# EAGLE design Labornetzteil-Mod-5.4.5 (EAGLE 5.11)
OC_FARNELL: unknown
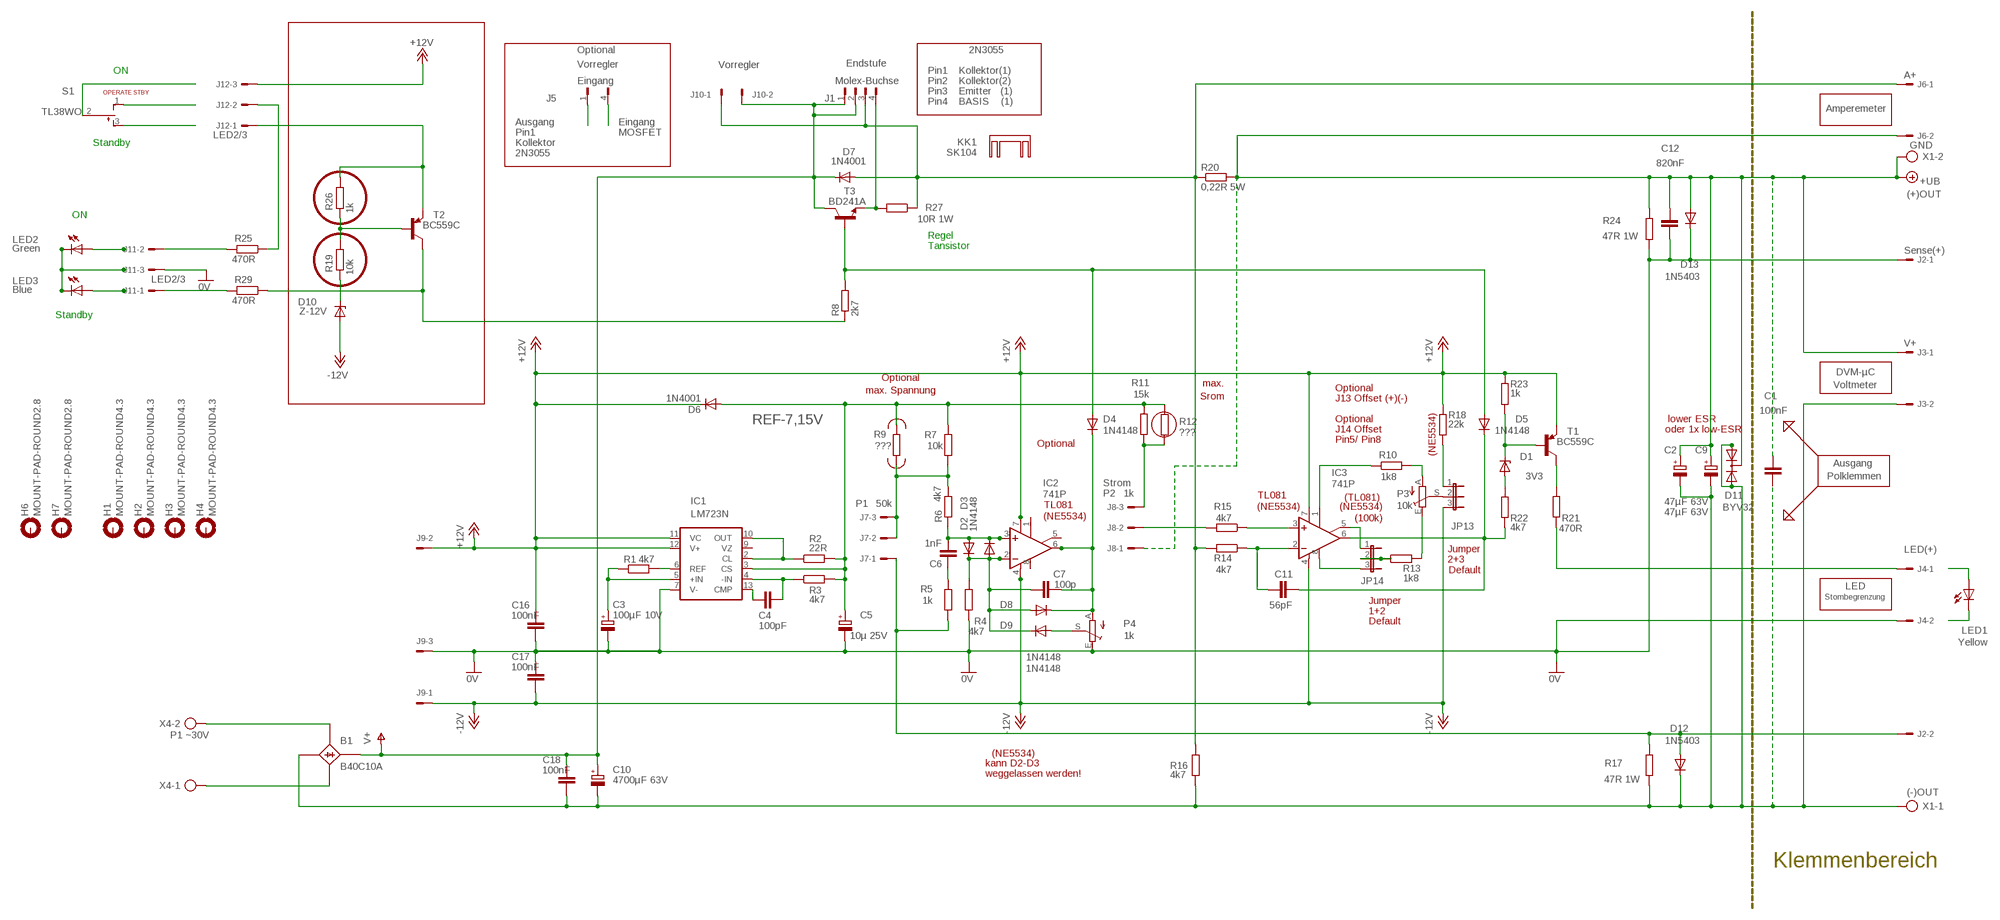
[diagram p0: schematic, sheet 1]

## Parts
B1  B40C10A  B25A-  [B25A-]
C1  100nF  C-EU025-024X044  [C025-024X044]
C2  47µF 63V  CPOL-EUE2.5-6  [E2,5-6]
C3  100µF 10V  CPOL-EUE5-8.5  [E5-8,5]
C4  100pF  C-EU025-024X044  [C025-024X044]
C5  10µ 25V  CPOL-EUE5-8.5  [E5-8,5]
C6  1nF  C-EU025-024X044  [C025-024X044]
C7  100p  C-EU025-024X044  [C025-024X044]
C9  47µF 63V  CPOL-EUE2.5-6  [E2,5-6]
C10  4700µF 63V  CPOL-EUE10-35  [EB35D]
C11  56pF  C-EU025-024X044  [C025-024X044]
C12  820nF  C-EU025-024X044  [C025-024X044]
C16  100nF  C-EU025-030X050  [C025-030X050]
C17  100nF  C-EU025-024X044  [C025-024X044]
C18  100nF  C-EUC1206K  [C1206K]
D1  3V3  ZENER-DIODEDO34-7  [DO34Z7]
D2  1N4148  1N4148DO35-10  [DO35-10]
D3  1N4148  1N4148DO35-10  [DO35-10]
D4  1N4148  1N4148DO35-10  [DO35-10]
D5  1N4148  1N4148DO35-10  [DO35-10]
D6  1N4001  1N4004  [DO41-10]
D7  1N4001  1N4004  [DO41-10]
D8  1N4148  DIODE-D-2.5  [D-2.5]
D9  1N4148  DIODE-D-2.5  [D-2.5]
D10  Z-12V  ZENER-DIODEZD-5  [ZDIO-5]
D11  BYV32  [TO220ABS]
D12  1N5403  DIODE-D-5  [D-5]
D13  1N5403  DIODE-D-5  [D-5]
H1  MOUNT-PAD-ROUND4.3  [4,3-PAD]
H2  MOUNT-PAD-ROUND4.3  [4,3-PAD]
H3  MOUNT-PAD-ROUND4.3  [4,3-PAD]
H4  MOUNT-PAD-ROUND4.3  [4,3-PAD]
H6  MOUNT-PAD-ROUND2.8  [2,8-PAD]
H7  MOUNT-PAD-ROUND2.8  [2,8-PAD]
IC1  LM723N  [DIL14]
IC2  741P  [DIL08]
IC3  741P  [DIL08]
J1  Endstufe  FLOPPY-4  [FLOPPY-4]
J2  Sense(+)  22-27-2021-02  [6410-02]
J3  V+  22-27-2021-02  [6410-02]
J4  LED(+)  22-27-2021-02  [6410-02]
J5  Vorregler  FLOPPY-4/2HALF  [FLOPPY-4/2]
J6  A+  22-27-2021-02  [6410-02]
J7  Spannung  22-27-2031-03  [6410-03]
J8  Strom  22-27-2031-03  [6410-03]
J9  -12V  22-27-2031-03  [6410-03]
J10  Vorregler  22-27-2021-02  [6410-02]
J11  LED2/3  22-27-2031-03  [6410-03]
J12  LED2/3  22-27-2031-03  [6410-03]
JP13  JP2E  [JP2]
JP14  JP2E  [JP2]
KK1  SK104  [SK104]
LED1  Yellow  LED5MM  [LED5MM]
LED2  Green  LED5MM  [LED5MM]
LED3  Blue  LED5MM  [LED5MM]
P3  10k  TRIM_EU-CA6V  [CA6V]
P4  1k  TRIM_EU-S63X  [S63X]
R1  4k7  R-EU_0204/2V  [0204V]
R2  22R  R-EU_0204/2V  [0204V]
R3  4k7  R-EU_0204/2V  [0204V]
R4  4k7  R-EU_0207/10  [0207/10]
R5  1k  R-EU_0207/10  [0207/10]
R6  4k7  R-EU_0207/10  [0207/10]
R7  10k  R-EU_0207/10  [0207/10]
R8  2k7  R-EU_0204/2V  [0204V]
R9  ???  R-EU_0207/10  [0207/10]
R10  1k8  R-EU_0207/10  [0207/10]
R11  15k  R-EU_0207/10  [0207/10]
R12  ???  R-EU_0207/10  [0207/10]
R13  1k8  R-EU_0207/10  [0207/10]
R14  4k7  R-EU_0207/10  [0207/10]
R15  4k7  R-EU_0207/10  [0207/10]
R16  4k7  R-EU_0207/10  [0207/10]
R17  47R 1W  R-EU_0207/10  [0207/10]
R18  22k  R-EU_0204/2V  [0204V]
R19  10k  R-EU_0204/2V  [0204V]
R20  0,22R 5W  R-EU_0617/22  [0617/22]
R21  470R  R-EU_0207/10  [0207/10]
R22  4k7  R-EU_0207/10  [0207/10]
R23  1k  R-EU_0207/10  [0207/10]
R24  47R 1W  R-EU_0207/10  [0207/10]
R25  470R  R-EU_0207/10  [0207/10]
R26  1k  R-EU_0204/2V  [0204V]
R27  10R 1W  R-EU_0309/10  [0309/10]
R29  470R  R-EU_0204/2V  [0204V]
S1  TL38WO  [TL3XWO]
T1  BC559C  -PNP-TO92  [TO92]
T2  BC559C  -PNP-TO92  [TO92]
T3  BD241A  2SC1307  [TO220AV]
X1  GND  AK300/2  [AK300/2]
X4  P1 ~30V  AK300/2  [AK300/2]

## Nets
0V: C3.- C5.- C12.2 C16.1 C17.2 D13.C IC1.7(V-) J2.1 J4.2 J9.3 J11.3 P4.E R4.1 R24.2
+12V: C16.2 D6.C IC1.11(VC) IC1.12(V+) IC2.7(V+) IC3.7(V+) J9.2 J12.3 R18.1 R23.1 T1.1(E)
-12V: C17.1 D10.A IC2.4(V-) IC3.4(V-) J9.1 JP13.3
-SENSE: D12.A J2.2 J7.1 R5.1 R17.1
N$1: C3.+ IC1.5(+IN) R1.1
N$2: JP13.1 R18.2
N$3: B1.AC1-(AC1) X4.2
N$4: B1.AC2-(AC2) X4.1
N$5: IC1.6(REF) R1.2
N$7: C6.1 R5.2
N$8: J7.2 J7.3 R6.2 R7.1 R9.1
N$9: IC1.2(CL) IC1.10(OUT) R2.1
N$10: C4.2 IC1.4(-IN) R3.1
N$11: J5.1
N$12: C4.1 IC1.13(CMP)
N$13: J4.1 R21.1
N$14: S1.2(P)
N$15: J12.2 R25.1
N$16: C7.1 D2.C D3.A D8.A D9.C IC2.2(-IN) R4.2
N$17: D4.A D5.A R8.2 T3.1(B)
N$18: C7.2 D4.C D8.C IC2.6(OUT) P4.A
N$19: J8.3 R11.1 R12.2
N$21: R21.2 T1.3(C)
N$22: C6.2 D2.A D3.C IC2.3(+IN) R6.1
N$23: D1.C R23.2 T1.2(B)
N$24: J8.2 R15.2
N$25: D1.A R22.1
N$26: J5.4
N$27: D7.A J1.3 J6.1 J10.1 R14.2 R16.1 R20.1 R27.1
N$29: C11.1 IC3.2(-IN) R14.1
N$30: JP14.2 R13.1
N$31: J12.1 R26.1 T2.1(E)
N$32: D10.C R19.2
N$33: IC3.3(+IN) R15.1
N$34: C11.2 D5.C IC3.6(OUT) R22.2
N$35: R19.1 R26.2 T2.2(B)
N$36: IC3.1(ON1) R10.1
N$37: S1.3(S)
N$39: LED1.A
N$40: LED2.K(C) LED3.K(C)
N$41: LED2.A
N$42: J1.4 R27.2 T3.3(E)
N$43: P3.E R13.2
N$44: P3.A R10.2
N$45: LED3.A
N$46: D9.A P4.S
N$48: J11.2 R25.2
N$49: J11.1 R29.2
N$50: JP13.2 P3.S
N$51: IC3.5(ON2) JP14.1
N$52: IC3.8(NC) JP14.3
N$53: LED1.K(C)
N$55: S1.1(O)
OUT+: C1.1 C2.+ C9.+ C12.1 D11.C D13.A J3.1 J6.2 J8.1 R20.2 R24.1 X1.2 ; supply symbol labelled +UB
OUT-: B1.-1(-) C1.2 C2.- C9.- C10.- C18.1 D11.A1 D11.A2 D12.C J3.2 R16.2 R17.2 X1.1
REF-7,15V: C5.+ D6.A IC1.3(CS) R2.2 R3.2 R7.2 R9.2 R11.2 R12.1
STBY: R8.1 R29.1 T2.3(C)
V+: B1.+1(+) C10.+ C18.2 D7.C J1.1 J1.2 J10.2 T3.2(C)
Unconnected: B1.+ B1.- B1.AC1 B1.AC2 H1.B4,3(MOUNT) H2.B4,3(MOUNT) H3.B4,3(MOUNT) H4.B4,3(MOUNT) H6.B2,8(MOUNT) H7.B2,8(MOUNT) IC1.9(VZ) IC2.1(ON1) IC2.5(ON2) IC2.8(NC)

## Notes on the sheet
- Optional | 2N3055
- ON | Pin1 | Kollektor(1)
- Eingang | Molex-Buchse | Pin2 | Kollektor(2)
- OPERATE STBY | Pin3 | Emitter   (1)
- Pin4 | BASIS    (1)
- Amperemeter
- Ausgang | Eingang
- Pin1 | MOSFET
- Standby | Kollektor
- 2N3055
- (+)OUT
- ON
- Regel
- Tansistor
- Standby
- DVM-µC
- Optional
- max. | Voltmeter
- max. Spannung | Optional
- Srom | J13 Offset (+)(-)
- Optional | lower ESR
- J14 Offset | oder 1x low-ESR
- Pin5/ Pin8
- Optional
- (NE5534)
- Ausgang
- Polklemmen
- Strom
- P2 | 1k | TL081
- (TL081)
- P1 | 50k | TL081
- (NE5534) | (NE5534)
- (NE5534) | (100k)
- Jumper
- 2+3
- Default
- LED
- Stombegrenzung
- Jumper
- 1+2
- Default
- (NE5534)
- kann D2-D3
- weggelassen werden!
- (-)OUT
- Klemmenbereich

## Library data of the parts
B1 = rectifier:B25A-: RECTIFIER 25-A bridge
C1 C4 C6 C7 C11 C12 C16-C18 = rcl:C-EU: CAPACITOR, European symbol
C2 C3 C5 C9 C10 = rcl:CPOL-EU: POLARIZED CAPACITOR, European symbol
D1 D10 = diode:ZENER-DIODE: Z-Diode
D2-D5 = diode:1N4148: DIODE
D6 D7 = diode:1N4004: DIODE
D8 D9 D12 D13 = diode:DIODE-: DIODE
D11 = diode:BYV32: DIODE 2 x Si diode 200 V, 20 A/230 Apeak, 25 ns
H1-H4 H6 H7 = holes:MOUNT-PAD-ROUND: MOUNTING PAD, round
IC1 = linear:*723: Positive VOLTAGE REGULATOR
IC2 IC3 = Labornetzteil:*741: OP AMP
J1 = con-amp:FLOPPY-4: MATE N-LOCK Floppy / HDD conector Distributor: Bürklin 71F970; OC_FARNELL: unknown; OC_NEWARK: unknown
J2-J4 J6 J10 = con-molex:22-?-02: CONNECTOR; OC_FARNELL: unknown; OC_NEWARK: unknown
J5 = Labornetzteil:FLOPPY-4/2
J7-J9 J11 J12 = con-molex:22-?-03: CONNECTOR wire to board 2.54 mm (.1 inch) pitch header; OC_FARNELL: unknown; OC_NEWARK: unknown
JP13 JP14 = jumper:JP2E: JUMPER
KK1 = heatsink:SK104: HEATSINK
LED1-LED3 = led:LED: LED
P3 P4 = pot:TRIM_EU-: POTENTIOMETER
R1-R27 R29 = rcl:R-EU_: RESISTOR, European symbol
S1 = switch:TL38WO: TINY SWITCH ON OFF MOM Source: http://www2.produktinfo.conrad.com/datenblaetter/700000-724999/705152-da-01-de-Subminiaturschalter_TL_36WO.pdf
T1 T2 = transistor:*-PNP-: PNP Transistror
T3 = transistor:2SC1307: NPN Transistor Silicon Epitaxial, High Frequency Power Amplifier Source: 2SC1307.pdf
X1 X4 = con-ptr500:AK300/2: CONNECTOR; OC_FARNELL: unknown; OC_NEWARK: unknown

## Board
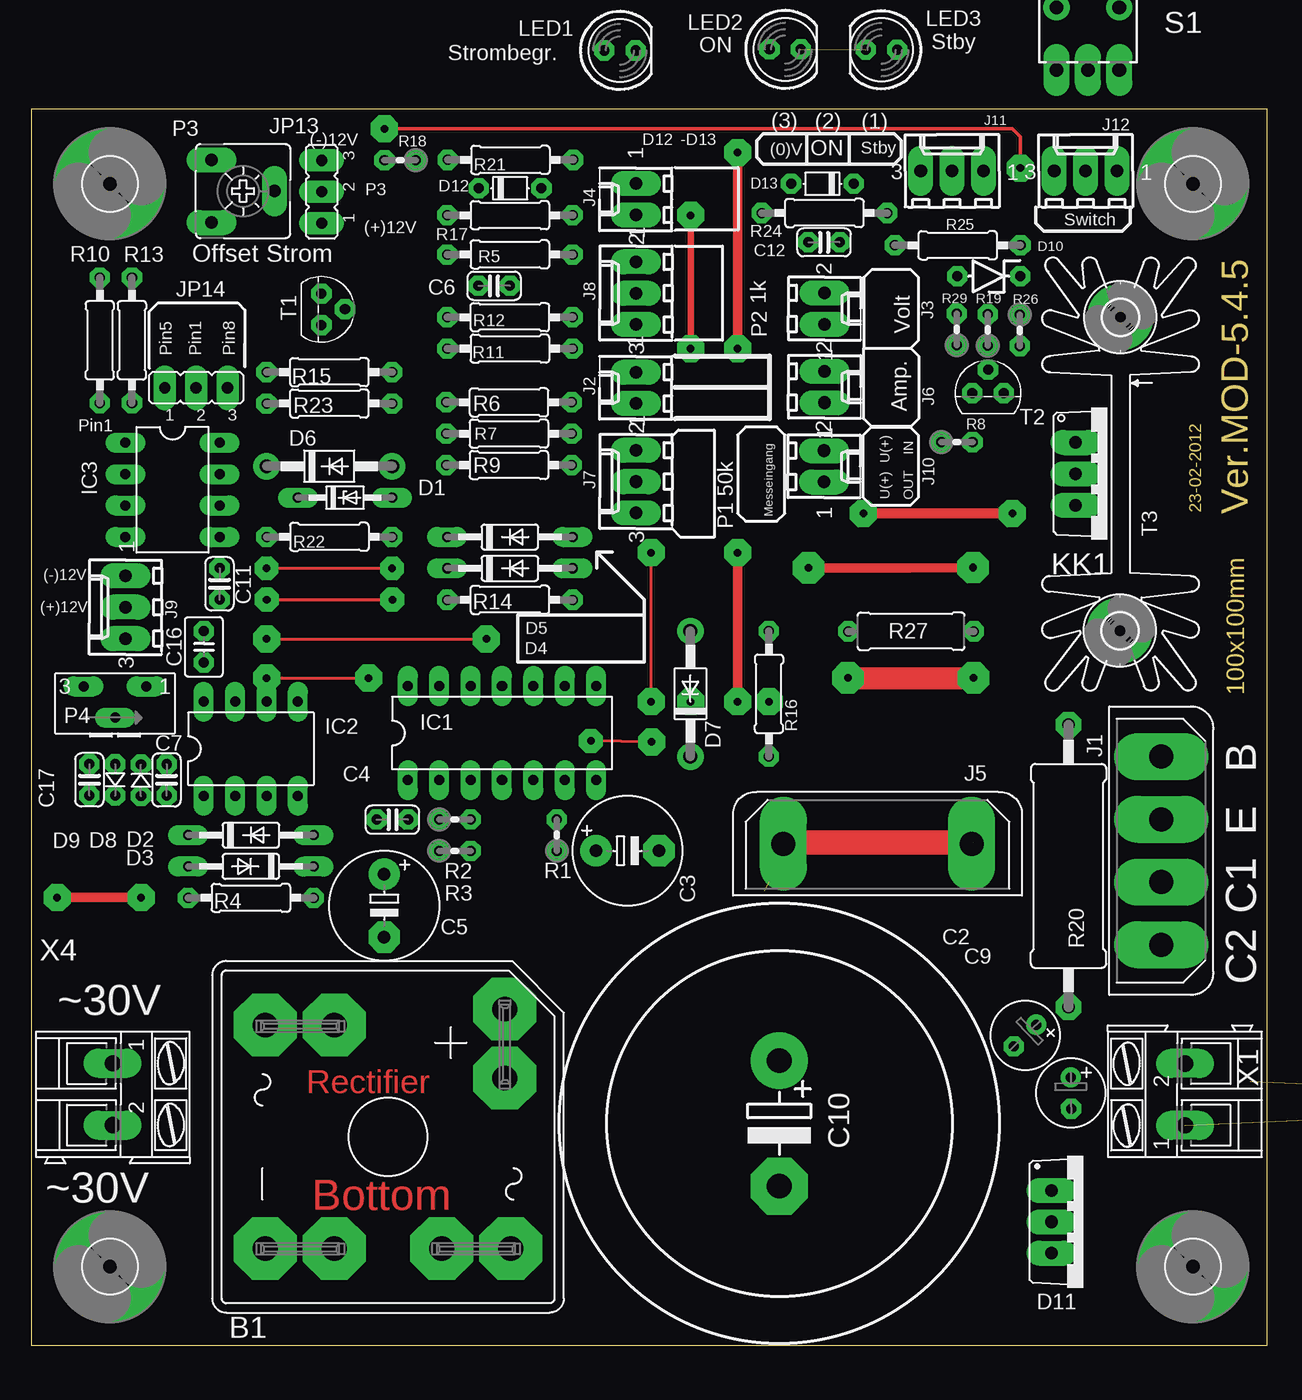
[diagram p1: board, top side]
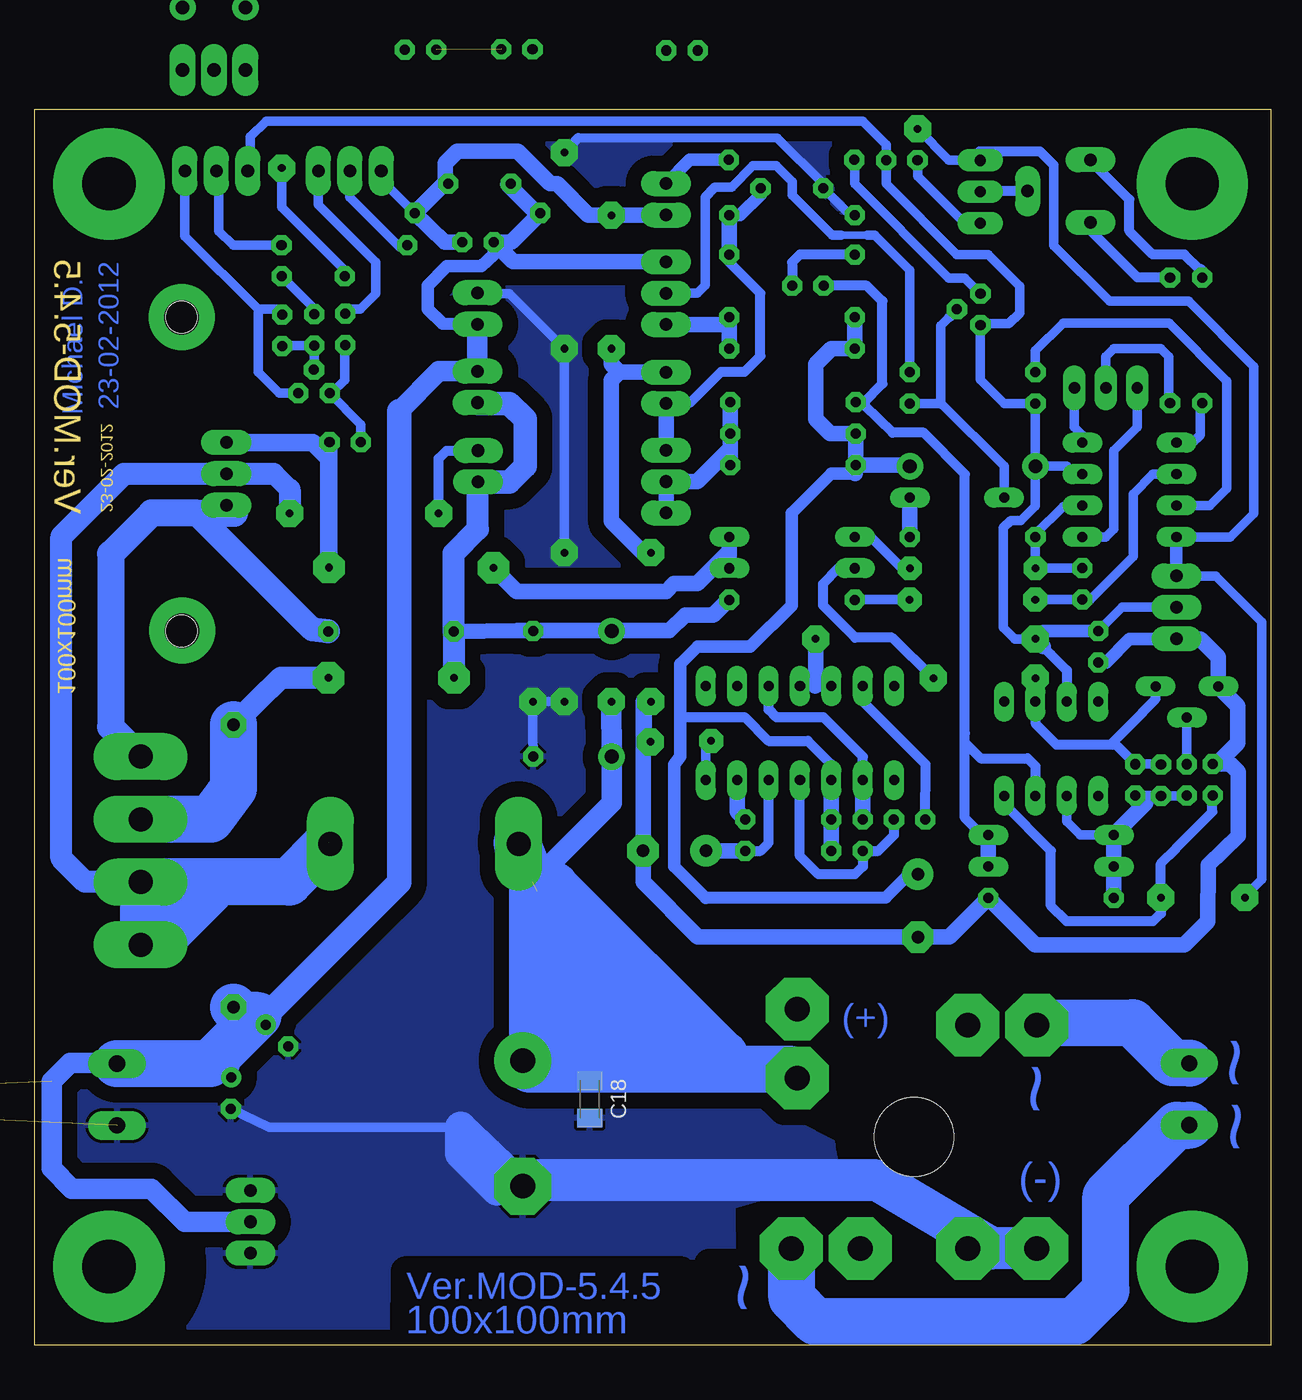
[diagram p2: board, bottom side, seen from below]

Size 100 x 100 mm. Coordinates in mm from the lower left corner, seen from the top.
Outline: 0,0 100,0 100,100 0,100 0,0
Copper layers (1*16): Top 0.035mm / dielectric 1.5mm / Bottom 0.035mm
Design rules "default *": minimum track width 30mil, minimum drill 24mil, track to track 8mil, track to pad 8mil, pad to pad 8mil, via to via 8mil, smd to smd 8mil, copper to edge 0.5mm, drill to drill 8mil, minimum pad ring 10mil, minimum via ring 8mil, stop-mask expansion 4mil, vias tented up to drill 0mil, thermal gap 10mil

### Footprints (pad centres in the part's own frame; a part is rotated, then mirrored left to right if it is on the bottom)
B25A- = drill 2.007 pad 5.08 octagon: + -10.338,9.449; +1 -4.75,9.449; - 9.042,-4.343; -1 9.042,-9.931; AC1 9.042,4.343; AC1- 9.042,9.931; AC2 -9.042,-4.343; AC2- -9.042,-9.931 | hole 6.401: 0,0
C025-024X044 = drill 0.813 octagon: 1 -1.27,0; 2 1.27,0
E2,5-6 = drill 0.813 pad 1.6 round: + -1.27,0 | drill 0.813 pad 1.6 octagon: - 1.27,0
E5-8,5 = drill 1.016 pad 2.54 round: + -2.54,0 | drill 1.016 pad 2.54 octagon: - 2.54,0
EB35D = drill 2.007 pad 4.597 round: + -5.08,0 | drill 2.007 pad 4.597 octagon: - 5.08,0
C025-030X050 = drill 0.813 octagon: 1 -1.27,0; 2 1.27,0
C1206K = smd 1.5 x 2: 1 -1.5,0; 2 1.5,0
DO34Z7 = drill 0.813 long: A 3.81,0; C -3.81,0
DO35-10 = drill 0.813 long: A 5.08,0; C -5.08,0
DO41-10 = drill 1.118 round: A 5.08,0; C -5.08,0
D-2.5 = drill 0.813 octagon: A 1.27,0; C -1.27,0
ZDIO-5 = drill 0.813 octagon: A 2.54,0; C -2.54,0
TO220ABS = drill 1.016 long: A1 -2.54,-2.54; A2 2.54,-2.54; C 0,-2.54
D-5 = drill 0.813 octagon: A 2.54,0; C -2.54,0
4,3-PAD = drill 4.3 pad 9 round: B4,3 0,0
2,8-PAD = drill 2.8 pad 5.334 round: B2,8 0,0
DIL14 = drill 0.813 long: 1 -7.62,-3.81; 2 -5.08,-3.81; 3 -2.54,-3.81; 4 0,-3.81; 5 2.54,-3.81; 6 5.08,-3.81; 7 7.62,-3.81; 8 7.62,3.81; 9 5.08,3.81; 10 2.54,3.81; 11 0,3.81; 12 -2.54,3.81; 13 -5.08,3.81; 14 -7.62,3.81
DIL08 = drill 0.813 long: 1 -3.81,-3.81; 2 -1.27,-3.81; 3 1.27,-3.81; 4 3.81,-3.81; 5 3.81,3.81; 6 1.27,3.81; 7 -1.27,3.81; 8 -3.81,3.81
FLOPPY-4 = drill 1.93 pad 3.81 long: 1 7.62,0; 2 2.54,0; 3 -2.54,0; 4 -7.62,0
6410-02 = drill 1.016 long: 1 1.27,0; 2 -1.27,0
FLOPPY-4/2 = drill 1.93 pad 3.81 long: 1 7.62,0; 4 -7.62,0
6410-03 = drill 1.016 long: 1 2.54,0; 2 0,0; 3 -2.54,0
JP2 = drill 0.914 long: 1 -2.54,0; 2 0,0; 3 2.54,0
SK104 = hole 2.54: -12.7,-0.762; 12.7,-0.762
LED5MM = drill 0.813 octagon: A -1.27,0; K 1.27,0
CA6V = drill 1.016 long: A -2.54,-2.54; E 2.54,-2.54; S 0,2.54
S63X = drill 0.813 long: A 2.54,0; E -2.54,0; S 0,-2.54
0204V = drill 0.813 octagon: 1 -1.27,0; 2 1.27,0
0207/10 = drill 0.813 octagon: 1 -5.08,0; 2 5.08,0
0617/22 = drill 1.016 octagon: 1 -11.43,0; 2 11.43,0
0309/10 = drill 0.813 octagon: 1 -5.08,0; 2 5.08,0
TL3XWO = drill 1.1 pad 1.422 long: 1 -2.54,-5.08; 2 0,-5.08; 3 2.54,-5.08 | drill 1.1 pad 1.676 round: M1 -2.54,0; M2 2.54,0
TO92 = drill 0.813 octagon: 1 1.27,0; 2 0,1.905; 3 -1.27,0
TO220AV = drill 1.016 long: 1 -2.54,-2.54; 2 0,-2.54; 3 2.54,-2.54
AK300/2 = drill 1.321 long: 1 -2.515,0; 2 2.489,0

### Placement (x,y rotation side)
B1  28.86,16.85 270 top
C1  not placed on the board
C2  80.4,25.05 224 top
C3  48.24,40.01 0 top
C4  29.21,42.53 0 top
C5  28.55,35.56 270 top
C6  37.45,85.72 180 top
C7  10.95,45.74 90 top
C9  84.11,20.4 270.5 top
C10  60.51,17.94 270 top
C11  15.23,61.6 90 top
C12  64.13,89.25 0 top
C16  13.96,56.51 90 top
C17  4.7,45.74 90 top
C18  55.09,19.88 90 bottom
D1  25.38,68.58 0 top
D2  17.76,41.27 0 top
D3  17.76,38.73 180 top
D4  38.72,62.87 0 top
D5  38.72,65.41 0 top
D6  24.11,71.12 0 top
D7  53.32,52.7 90 top
D8  8.88,45.71 270 top
D9  6.79,45.74 90 top
D10  77.47,86.5 180 top
D11  85.09,9.97 270 top
D12  38.73,93.61 0 top
D13  64.01,93.99 180 top
H1  6.35,93.98 0 top
H2  6.35,6.35 0 top
H3  93.98,93.98 0 top
H4  93.98,6.35 0 top
H6  88.12,83.19 0 top
H7  88.07,57.82 0 top
IC1  38.08,49.53 0 top
IC2  17.76,48.26 0 top
IC3  11.43,69.22 270 top
J1  91.42,40.01 270 top
J2  48.91,77.47 90 top
J3  64.17,83.89 270 top
J4  48.91,92.73 90 top
J5  68.46,40.56 0 top
J6  64.17,77.55 270 top
J7  48.92,69.88 90 top
J8  48.92,85.13 90 top
J9  7.62,59.72 90 top
J10  64.14,71.12 270 top
J11  74.5,95.02 0 top
J12  85.3,95.02 0 top
JP13  23.5,93.34 90 top
JP14  13.34,77.47 0 top
KK1  88.88,70.49 270 top
LED1  not placed on the board
LED2  not placed on the board
LED3  not placed on the board
P3  17.13,93.39 270 top
P4  6.78,53.32 0 top
R1  42.53,41.27 90 top
R2  34.27,42.55 0 top
R3  34.27,40.01 0 top
R4  17.76,36.2 180 top
R5  38.72,88.27 180 top
R6  38.65,76.3 0 top
R7  38.65,73.76 180 top
R8  74.88,73.07 0 top
R9  38.65,71.22 180 top
R10  5.54,81.32 90 top
R11  38.72,80.64 180 top
R12  38.72,83.19 0 top
R13  8.15,81.32 90 top
R14  38.72,60.31 0 top
R15  24.11,78.74 0 top
R16  59.67,52.7 270 top
R17  38.72,91.44 180 top
R18  29.84,95.89 180 top
R19  77.37,82.16 90 top
R20  83.91,38.78 270 top
R21  38.76,95.92 180 top
R22  24.11,65.41 180 top
R23  24.11,76.2 0 top
R24  64.17,91.62 0 top
R25  74.95,89 180 top
R26  79.98,82.12 270 top
R27  71.18,57.77 0 top
R29  74.86,82.2 90 top
S1  not placed on the board
T1  23.48,83.82 270 top
T2  77.4,77.03 0 top
T3  87.04,70.52 270 top
X1  93.33,20.29 90 top
X4  6.59,20.29 270 top

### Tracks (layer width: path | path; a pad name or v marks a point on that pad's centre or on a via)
0V  (via drill 0.61 pad 1.93, 0.61 pad 2.18)
  Top 0.254: v50.15,52.07 v50.15,64.14 | v50.19,48.81 v45.27,48.9
  Top 0.508: v53.34,80.64 v53.34,91.44
  Bottom 0.254: v50.19,48.81 50.19,50.12 v50.15,52.07
  Bottom 0.762: IC1.7 45.7,48.51 v45.27,48.9 | J11.3 71.96,94.34 R24.2 | D13.C 66.56,93.98 66.8,93.98 66.89,93.98 66.9,93.97
  Bottom 1.016: 50.78,52.08 v50.15,52.07 | 48.92,91.48 48.88,91.48 J4.2 | J2.1 50.79,78.74 50.86,78.74 | 50.19,63.53 50.19,63.54 v50.15,64.14 | 11.46,57.16 J9.3 | 11.46,57.16 13.31,55.25 C16.1 | 5.72,57.16 11.46,57.16
  Bottom 1.27: 50.78,52.08 C3.- 50.78,37.47 46.34,33.02 C5.- 26.02,33.02 R4.1 22.84,36.18 19.06,32.4 6.99,32.4 5.08,34.31 5.04,38.85 2.65,41.22 2.63,46.4 3.27,47.03 4.42,47.03 C17.2 4.4,46.99 2.66,48.73 2.66,51.74 P4.E 4.24,55.68 5.72,57.16 | C12.2 66.81,89.25 R24.2 66.9,93.97 | 66.8,93.98 66.8,95.64 65.83,96.61 60.91,96.61 58.28,93.98 57.73,93.98 55.21,91.46 J4.2 53.32,91.46 v53.34,91.44 | v53.34,80.64 53.34,79.38 52.7,78.74 J2.1 | 50.79,78.74 52.71,78.74 53.34,78.11 53.34,66.67 50.8,64.14 v50.15,64.14
+12V  (via drill 0.61 pad 2.18)
  Top 0.254: v19.03,57.15 v36.81,57.15
  Bottom 0.762: T1.1 23.51,82.52 23.51,78.14 21.57,76.2 R23.1 D6.C | D6.C 19,71.15 16.52,71.15 15.85,70.48 IC3.7 | C16.2 12.02,59.72 J9.2 | 17.75,55.87 v19.03,57.15 20.69,57.15 21.62,58.08 21.62,66.16 21.05,66.73 20.22,66.73 19.03,67.92 D6.C | T1.1 | T1.1 23.38,82.65 21.19,82.65 20.31,83.53 20.31,85.72 22.86,88.27 25.4,88.27 31.11,93.98 R18.1 31.11,97.16 33.02,99.06 81.28,99.06 82.55,97.79 82.55,95.23 J12.3
  Bottom 0.813: IC1.12 36.85,53.34 IC1.11 | IC2.7 16.49,54.61 v19.03,57.15
  Bottom 1.016: C16.2 18.41,57.77 v19.03,57.15
  Bottom 1.27: v19.03,57.15 18.4,56.52 | v36.81,57.15 36.81,53.38 36.85,53.34
-12V  (via drill 0.61 pad 2.18)
  Top 0.3: v28.57,98.42 79.38,98.42 80.01,97.79 v80.01,95.25
  Top 0.762: v2.09,36.21 v8.89,36.21
  Bottom 0.762: J9.1 4.45,62.26 0.73,58.52 0.74,37.7 2.09,36.34 v2.09,36.21 | 17.56,95.51 17.56,88.99 13.01,84.48 6.65,84.48 1.36,79.19 1.36,67.31 3.28,65.39 7.62,65.39 | 8.21,65.39 7.62,65.39 | 23.57,96.59 23.5,96.03 JP13.3 26.04,95.89 v28.57,98.42 | v80.01,95.25 80.01,92.08 74.93,87 D10.A | 7.62,65.39 IC3.4 | 8.21,65.39 8.22,65.39 | 7.92,65.1 8.21,65.39
  Bottom 0.813: C17.1 4.72,43.15 7.63,40.24 7.62,40.25 8.89,38.98 v8.89,36.22 v8.89,36.21 8.89,34.92 9.53,34.29 16.51,34.29 17.78,35.56 17.78,40.01 21.57,43.8 IC2.4 | 17.56,95.51 18.65,96.59 23.57,96.59
  Bottom 1.016: IC2.4 21.57,43.42 | 7.62,64.8 7.92,65.1 | 7.62,64.8 7.59,64.77 | J9.1 7.62,64.8
-SENSE
  Bottom 0.762: 43.8,87.63 R5.1 | J2.2 48.87,76.24 | 41.27,93.1 D12.A
  Bottom 0.813: 43.8,87.63 41.29,85.13 41.29,80.05 42.56,78.78 44.47,78.78 47.01,76.24 48.87,76.24
  Bottom 1.016: 43.55,91.36 R17.1 42.94,91.43 41.27,93.1
  Bottom 1.27: R5.1 R17.1 | J2.2 48.91,72.43 J7.1
N$1
  Bottom 0.813: IC1.5 40.62,40.64 41.26,40.01 R1.1
  Bottom 1.27: R1.1 C3.+
N$2
  Bottom 0.762: R18.2 28.57,94.61 24.77,90.81 JP13.1
N$3
  Bottom 3.81: X4.2 7.6,17.8 13.34,12.06 13.34,4.45 15.88,1.91 36.83,1.91 38.73,3.81 38.73,7.75 B1.AC1-
N$4
  Bottom 3.81: X4.1 7.95,22.85 11.18,26.08 18.79,26.04 B1.AC2-
N$5
  Bottom 1.27: R1.2 43.16,43.18 IC1.6
N$7
  Bottom 0.813: C6.1 38.72,87.63 38.08,88.27 R5.2
N$8
  Bottom 0.762: 43.8,72.46 43.8,73.66
  Bottom 1.27: R7.1 43.73,73.73 43.8,73.66 | R7.1 R9.1 | R7.1 R6.2 | 43.8,72.46 46.38,69.88 J7.2 J7.3
N$9
  Bottom 0.813: IC1.10 40.62,51.44 39.99,50.8 36.18,50.8 33,47.62 IC1.2
  Bottom 1.27: R2.1 IC1.2
N$10
  Bottom 0.813: C4.2 30.46,41.27 31.73,40.01 R3.1 33,38.73 33.64,38.1 36.6,38.1 38.08,39.58 IC1.4
N$12
  Bottom 0.813: C4.1 27.92,46.99 33,52.07 IC1.13
N$13
  Bottom 1.016: R21.1 47.02,95.92 J4.1
N$15
  Bottom 0.762: R25.1 83.92,89 85.09,90.17 85.09,94.81 J12.2
N$16
  Bottom 0.762: C7.1 9.71,44.46 | C7.1 9.54,44.47 D8.A 6.82,44.44 D9.C | 10.13,44.23 10.15,44.41 C7.1 | IC2.2 16.49,42.39 15.39,41.29 12.7,41.29 D2.C
  Bottom 1.27: D2.C D3.A R4.2 | D2.C | D2.C 10.12,43.87 10.13,44.23 | C7.1 11,44.22
N$17  (via drill 0.61 pad 2.54)
  Top 0.762: v62.89,62.9 71.09,62.9 v76.2,62.93
  Bottom 0.762: v76.2,62.93 76.15,62.92
  Bottom 1.27: D4.A D5.A 43.8,64.2 46.38,61.62 48.28,61.62 48.92,60.99 60.98,60.99 v62.89,62.9
  Bottom 1.422: 76.15,73.06 R8.2 76.2,73.07 76.2,71.75 | v76.2,62.93 76.2,71.75 | T3.1 77.5,73.06 76.2,71.75
N$18  (via drill 0.61 pad 2.18)
  Top 0.254: v19.03,53.98 v27.29,53.98
  Bottom 0.61: 18.99,50.93 IC2.6
  Bottom 0.762: 34.97,62.87 D4.C | C7.2 8.91,47.01 D8.C
  Bottom 0.813: IC2.6 v19.03,53.98 | 12.98,48.58 12.5,48.58 C7.2 | 12.98,48.58 17.32,48.58 19,50.26 18.99,50.93 | 34.97,62.87 36.21,61.62 36.21,59.85 33.61,57.26 30.64,57.26 v27.29,53.98 | P4.A 9.32,52.29 10.39,51.22 10.39,51.17 12.98,48.58
N$19
  Bottom 1.27: R11.1 43.8,82.59 | 43.8,82.59 R12.2 | J8.3 43.8,82.59
N$20
  Bottom 3.81: 91.48,32.4 90.21,32.4 85.77,36.85
N$21
  Bottom 0.762: T1.3 23.51,85.12 23.51,85.13 23.54,85.13 24.77,86.36 26.04,86.36 33.66,93.98 33.66,95.89 R21.2
N$22
  Bottom 0.61: R6.1 32.9,76.3
  Bottom 0.762: 32.83,76.03 32.83,76.2 | 24.75,49.53 24.77,49.55
  Bottom 0.813: 33.74,76.3 R6.1 32.83,76.2 33,76.2 | IC2.3 19.03,46.86 19.67,47.49 23.48,47.49 24.75,48.76 | C6.2 32.68,85.72 31.41,84.51 31.41,77.79 32.9,76.3 | 22.84,40.77 24.75,42.67 24.75,48.76 | 24.75,48.76 24.75,49.53 24.75,70.49 28.05,73.85 30.6,73.85 32.83,76.03
  Bottom 1.27: D3.C 22.84,40.77 D2.A
N$23
  Bottom 0.762: 27.35,76.2 R23.2 | 26.68,76.24 27.35,76.2 | 26.68,76.24 26.68,82.52 26.02,83.19 | D1.C 21.57,71.12 26.68,76.24 | 26.68,76.24 26.68,76.17 27.35,76.2
  Bottom 0.813: T1.2 26.02,83.19
N$24
  Bottom 0.61: 32.66,89.83 34.73,89.83
  Bottom 0.762: J8.2 46.38,85.13 45.74,85.77 45.74,92.9 44.99,93.73 43.61,93.73 41.89,95.45 40.02,95.45 38.71,94.14 38.71,93.06 35.47,89.81 34.74,89.81 34.73,89.83 | R15.2 29.19,87 32.02,89.83 32.66,89.83
N$25
  Bottom 1.27: R22.1 D1.A
N$27  (via drill 0.61 pad 2.54)
  Top 1.778: v66.07,54 v76.24,54
  Bottom 0.762: 60.97,57.81 57.16,57.81 R16.1 D7.A
  Bottom 1.27: R14.2 43.88,60.31 45.11,59.08 47.37,59.08 48.64,57.81 60.97,57.81 R27.1
  Bottom 1.778: R27.1 66.1,54.03 v66.07,54 | v76.24,54 80.08,54 R20.1
  Bottom 1.8: R27.1 66.1,64.08 64.14,66.04 J10.1
  Bottom 1.9: J10.1 61.59,69.85 60.33,71.12 60.33,74.93 61.59,76.2 64.1,76.2 J6.1
  Bottom 3.81: J1.3 85.85,42.55 85.76,42.57 83.91,45.05 R20.1
N$28  (via drill 2 pad 3.3)
  other vias: 28.86,16.86
N$29  (via drill 0.61 pad 1.93)
  Top 0.254: v19.05,60.33 v29.21,60.33
  Bottom 0.762: 15.87,60.33 14.61,60.33 11.12,63.81 11.12,68.89 9.53,70.48 IC3.2 | 15.87,60.33 v19.05,60.33 | v29.21,60.33 33.63,60.33 R14.1 | C11.1 15.87,60.33
N$30
  Bottom 0.762: R13.1 8.26,76.24 8.26,80.01 8.89,80.64 12.7,80.64 13.34,80.01 JP14.2
N$31
  Bottom 0.762: J12.1 87.84,89.74 81.92,83.82 | 81.92,83.82 80.26,83.82 R26.1 | T2.1 80.2,77.03 81.92,78.74 81.92,83.82
N$32
  Bottom 0.762: R19.2 77.37,83.86 D10.C
N$33
  Bottom 0.762: R15.1 19.03,80.48 16.8,82.7 8.19,82.7 3.56,78.03 3.56,69.32 4.92,67.96 7.58,67.96 7.62,67.96 IC3.3
N$34  (via drill 0.61 pad 1.93)
  Top 0.254: v19.03,62.87 v29.19,62.87
  Bottom 0.762: R22.2 v19.03,62.87 | 33.01,65.41 D5.C 33.61,65.44 | v29.19,62.87 29.83,62.87 | R22.2 19.03,62.92 19.06,62.9 15.84,62.9 15.86,62.87 C11.2 | R22.2 19.03,65.64 16.8,67.87 15.93,67.87 15.86,67.94 IC3.6
  Bottom 0.813: 29.83,62.87 32.4,65.44 33.61,65.44
N$35
  Bottom 0.762: T2.2 77.37,78.97 R19.1 79.17,80.89 R26.2
N$36
  Bottom 0.762: 5.47,75.82 R10.1 5.71,76.07 5.71,73.66 6.35,73.03 IC3.1
N$40  (1 unrouted)
N$42
  Bottom 0.762: T3.3 84.45,67.98 84.45,67.94 83.82,67.94 83.82,67.31
  Bottom 1.93: R27.2 77.53,57.92 86.95,67.34
  Bottom 2.184: J1.4 91.42,47.59 93.86,50.03 93.86,64.02 90.54,67.34 86.95,67.34 83.82,67.34 83.82,67.31
N$43
  Bottom 0.813: R13.2 10.77,86.4 11.79,87.43 15.17,90.8 P3.E
N$44
  Bottom 0.813: 14.59,95.87 11.43,92.71 11.43,90.17 9.53,88.27 6.99,88.27 5.71,87 | R10.2 5.71,86.57
  Bottom 1.016: 14.59,95.87 P3.A | 5.71,86.57 5.71,87
N$46
  Bottom 0.762: P4.S 6.78,47.02 D9.A
N$48
  Bottom 0.762: J11.2 74.5,92.91 70.48,88.9 70.12,88.9 R25.2
N$49
  Bottom 0.762: J11.1 77.04,92.28 72.39,87.63 72.39,85.09 73.66,83.82 74.52,83.82 R29.2
N$50
  Bottom 0.813: P3.S 23.45,93.39 JP13.2
N$51
  Bottom 0.762: JP14.1 10.79,74.3 12.7,72.39 12.7,66.04 13.34,65.41 IC3.5
N$52
  Bottom 0.762: 15.86,77.47 JP14.3 15.88,74.3 15.24,73.66 IC3.8
OUT+  (1 unrouted)
  Bottom 0.762: R20.2 82.52,25.95 C9.+ 84.43,22.01 84.43,22.66 81.31,25.78 C2.+ | 61.72,93.95 61.5,93.95 D13.A
  Bottom 1.016: J3.1 66.99,82.65 68.19,83.85 68.19,85.75 66.64,87.34 63.85,87.31 62.87,88.27 62.87,88.92 C12.1
  Bottom 1.27: J3.1 64.1,82.54 | 61.72,93.95 59.62,91.85 59.31,91.85 R24.1 61.44,89.25 C12.1 61.28,87.67 J8.1
  Bottom 1.676: J3.1 J6.2 67.3,78.81 70.52,75.6 | D11.C 87.87,9.97 90.56,12.66 96.98,12.66 98.63,14.3 98.63,21.36 97.13,22.85 93.4,22.85 X1.2
  Bottom 2: 70.52,75.6 70.52,37.43 81.92,26.04 82.6,26.04 R20.2
  Bottom 3.81: X1.2 85.8,22.78 81.92,26.67 83.24,26.67 R20.2
OUT-  (via drill 0.61 pad 2.18)  (1 unrouted)
  Top 0.762: v57.15,80.64 v57.15,96.52 | v57.15,52.07 v57.15,64.14
  Bottom 0.762: R16.2 59.69,49.55 v59.69,52.07 v57.15,52.07 | 65.54,17.62 81.02,17.62 C9.- | R17.2 33.88,91.44 | J3.2 64.11,85.09 61.59,85.09 v57.15,80.64 v57.15,64.14 | v57.15,96.52 56.01,97.7 39.92,97.66 36.16,93.94 36.2,93.91 | 33.92,91.44 34.02,91.44 D12.C
  Bottom 1.016: 33.88,91.44 33.92,91.44
  Bottom 2.54: 62.58,12.58 65.54,15.54 65.54,17.62 C10.-
  Bottom 3.4: B1.-1 22.58,7.81 31.84,13.33 59.4,13.33 C10.-
  pour Bottom (isolate 1.27): -1.27,100.97 -1.27,88.9 31.75,88.9 31.98,37.47 31.98,37.32 31.76,31.84 39.38,31.8 44.01,26.61 43.91,24.84 43.81,20.76 31.96,14.6 43.55,11.23 43.42,-1.01 101.23,-0.92 101.71,101.24
REF-7,15V
  Bottom 0.762: 29.29,71.22 D6.A
  Bottom 0.813: IC1.3 35.54,46.99 37.45,48.9 40.64,48.9 42.56,50.82 47.75,50.82
  Bottom 1.016: C5.+ 29.22,38.12 31.13,36.21 45.7,36.2 48.24,38.73 48.24,46.99 47.75,47.62 47.75,50.82 47.75,55.1 46.34,56.52 42.1,56.52 38.75,59.87 38.75,67.34 35.55,70.55 33.6,70.55
  Bottom 1.27: 33.6,70.55 R9.2 | R9.2 R7.2 35.64,73.76 36.81,74.93 36.81,79.38 35.54,80.64 R11.2 R12.1 | R9.2 29.29,71.22 | R3.2 R2.2 IC1.3
STBY
  Bottom 0.762: R8.1 73.61,74.5 T2.3 76,77.03 74.93,78.11 74.93,80.87 R29.1
V+  (via drill 0.61 pad 2.18)  (2 unrouted)
  Top 0.813: v79.38,67.31 v67.31,67.31
  Top 2: v60.99,40.66 74.3,40.66 76.2,40.66 76.24,40.66
  Bottom 0.762: C18.2 55.09,21.52 60.51,21.52 C10.+ | 76.24,40.66 76.82,40.66 79.38,38.1 | 80.01,37.47 79.38,38.1 | 79.38,38.1 78.8,38.1 76.24,40.66 | 76.24,40.66 76.2,40.66
  Bottom 0.813: J10.2 66.67,72.39 67.31,71.75 v67.31,67.31
  Bottom 1.676: 53.32,47.61 53.32,43.88 59.72,37.48 | 53.32,47.61 D7.C | 53.32,47.61 v53.34,52.07 | 80.68,70.52 80.64,70.52 79.38,69.25
  Bottom 1.778: J1.2 91.43,37.48 95.93,37.48 97.84,39.39 97.84,65.44 92.75,70.52 T3.2
  Bottom 1.8: T3.2 80.68,70.52 | 79.38,69.25 v79.38,67.31
  Bottom 3.4: J1.2 J1.1
  Bottom 3.81: J1.2 79.42,37.47 76.24,40.66 | v60.99,40.66 59.72,37.48 59.71,22.92 C10.+ 60.59,22.94 59.96,22.32 38.95,22.32 B1.+1 | 59.35,36.76 57.92,37.17 44.2,23.5 57.25,23.8 57.25,34.04 57.2,34.09 57.05,34.09 48.51,25.55 52.57,25.55 55.6,28.59
(copper drawn outside any net)
  shapes: Bottom circle x4

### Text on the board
Top: Rectifier | Bottom
Bottom: 23-02-2012 | Michael D. | (+) | ~ | ~ | ~ | (-) | Ver.MOD-5.4.5 | ~ | 100x100mm
Dimension: Ver.MOD-5.4.5 | 23-02-2012 | 100x100mm
tPlace: ON | Stby | Strombegr. | (3) | (2) | (1) | (-)12V | ON | -D13 | (0)V | Stby | P3 | D12 | Switch | (+)12V | Offset Strom | 1k | P2 | Volt | Pin5 | Pin1 | Pin8 | Amp. | Pin1 | U(+) | IN | U(+) | OUT | Messeingang | P1 50k | (-)12V | (+)12V
bOrigins: optional | Vorregler
tNames: B | E | C1 | ~30V | C2 | ~30V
